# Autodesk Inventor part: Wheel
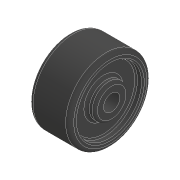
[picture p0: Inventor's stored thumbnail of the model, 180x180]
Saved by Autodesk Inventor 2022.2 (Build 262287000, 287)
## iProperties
Created: 2021-12
Part Number: Wheel
Material: ナイロン 6/6
Document SubType Name: Modeling
Designer: taeku
Mass: 110.761 g
Surface Area: 127.395 cm^2
Volume: 71.8758 cm^3
Density: 1.13 g/cm^3
Appearance: ゴム - 黒
Author: taeku
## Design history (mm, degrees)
sketch "スケッチ1"
  geometry: C1 r 30 at (0, 0); 1 further point
  constraints: 1 centre point, 1 coincident
  dimensions: "d0" = 60 diameter of C1
extrude "押し出し1" new body sketch "スケッチ1" stored distance "d1" = 30; taper "d2" = 0 deg
sketch "スケッチ2"
  geometry: C1 r 24.026 at (0, 0); 1 further point
  constraints: 1 centre point, 1 coincident
extrude "押し出し2" cut sketch "スケッチ2" distance "d3" = 5; taper "d4" = 0 deg
sketch "スケッチ3"
  geometry: C1 r 12.5 at (0, 0); 1 further point
  constraints: 1 centre point, 1 coincident
  dimensions: "d5" = 25 diameter of C1
extrude "押し出し3" join sketch "スケッチ3" distance "d6" = 6; taper "d7" = 0 deg
fillet "フィレット1" dims "d8" = 2, "d9" = 1
mirror "ミラー1"
fillet "フィレット2" dims "d10" = 1
fillet "フィレット3" dims "d11" = 3
sketch "スケッチ4"
  geometry: C1 r 12.5 at (0, 0) reference; 2 further points
  constraints: 1 coincident
hole "穴1" sketch "スケッチ4" at (0, 0) diameter "d12" = 12; stored, may be unused: countersink angle "d16" = 90 deg, drill point angle "d18" = 118 deg; dims "d13" = 15, "d14" = 4, "d15" = 2, "d17" = 14.2
node "ソリッド1"
